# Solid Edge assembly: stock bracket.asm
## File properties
Author: Deepak Maini
Template: normal.asm
Last saved by: MYPC
Revision: 5
Application: Solid Edge
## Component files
adjusting_nut_handle.par
adjusting_screw_guide.par
Stock_support_base.par
thrust_bearing.par
adjusting_screw_nut.par
support_adjusting_screw.par
support_roller_bracket.par
stock_support_roller.par
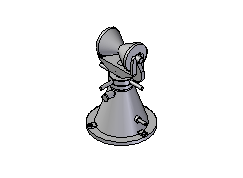
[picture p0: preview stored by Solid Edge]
